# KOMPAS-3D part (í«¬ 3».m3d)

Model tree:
1. Эскиз:1
2. Операция выдавливания:1
     Расстояние 1 = 2
3. Эскиз:2
4. Операция выдавливания:2
     Расстояние 1 = 5
5. Эскиз:3
6. Операция выдавливания:3
     Расстояние 1 = 2
7. Эскиз:4
8. Операция выдавливания:4
     Расстояние 1 = 60
9. Эскиз:5
10. Операция выдавливания:5
     Расстояние 1 = 2
11. Эскиз:6
12. Операция выдавливания:6
     Расстояние 1 = 4.5
13. Эскиз:7
14. Операция выдавливания:7
     Расстояние 1 = 2
15. Скругление:1
     Радиус = 1
16. Скругление:2
     Радиус = 1
17. Эскиз:8
18. Вырезать элемент выдавливания:1
     Расстояние 1 = 10; Угол 1 = 35
19. Эскиз:9
20. Вырезать элемент выдавливания:2
     Расстояние 1 = 10; Угол 1 = 35
21. Эскиз:10
22. Вырезать элемент выдавливания:3
     Расстояние 2 = 22; Расстояние 1 = 22; Угол 1 = 35
23. Эскиз:11
24. Вырезать элемент выдавливания:4
     Расстояние 2 = 2; Расстояние 1 = 2
25. Эскиз:12
26. Вырезать элемент выдавливания:5
     Расстояние 2 = 2; Расстояние 1 = 2; Угол 1 = 35
27. Эскиз:13
28. Вырезать элемент выдавливания:6
     Расстояние 2 = 2; Расстояние 1 = 122
29. Эскиз:15
30. Операция выдавливания:9
     Расстояние 1 = 10; Расстояние 2 = 0.5
